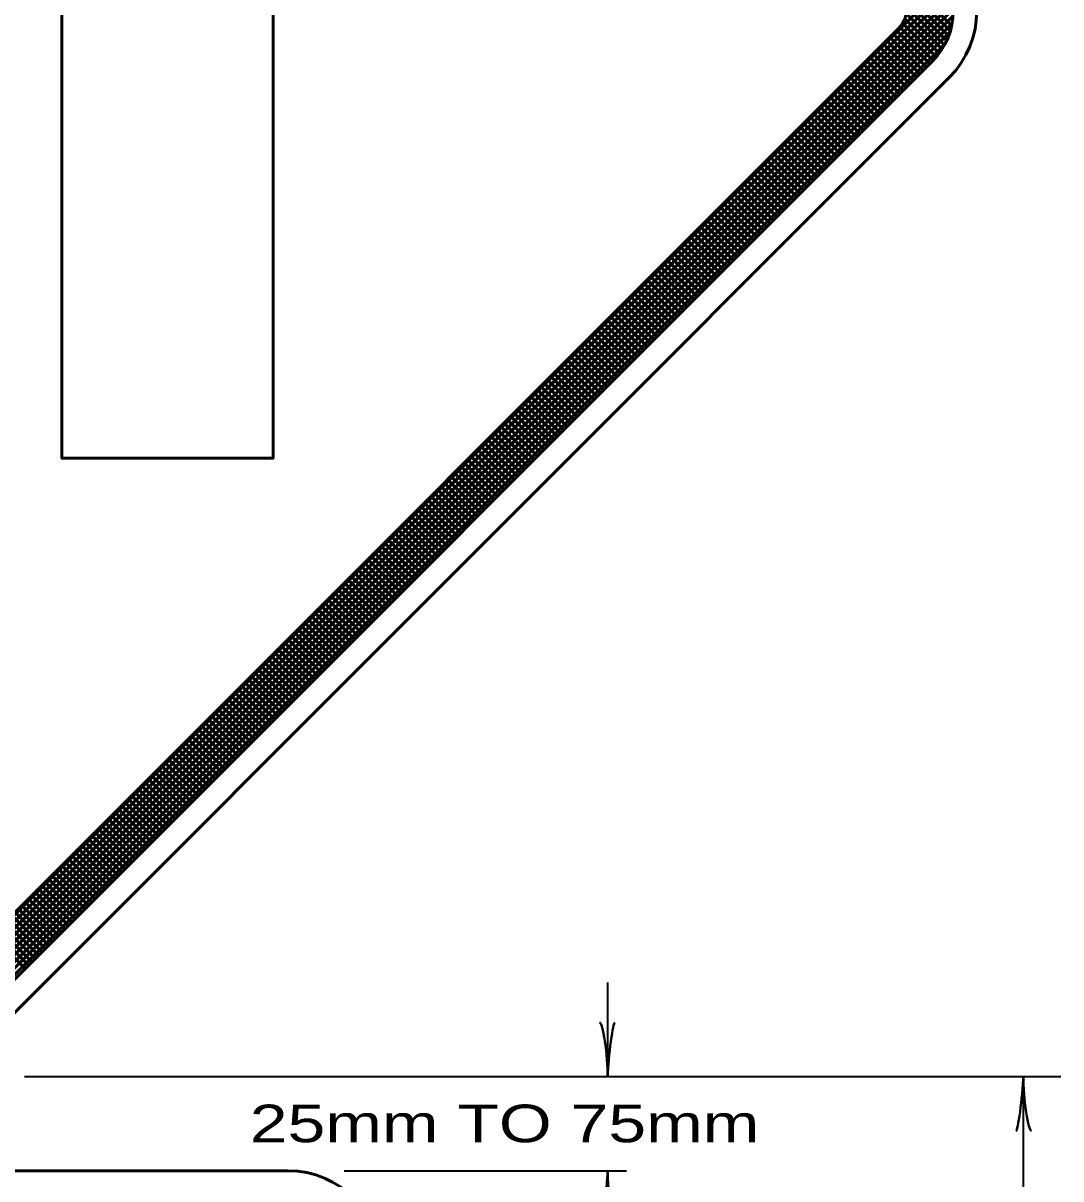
# Model space of a CAD drawing. Extents: x -87 to 768, y -466 to 78.
# Drawn here: x 67 to 133.2, y -203.4 to -129.7 of the extents above; entities that cross this region are included whole.
import ezdxf
from ezdxf.enums import TextEntityAlignment as Align

# ---------------------------------------------------------------- set-up
doc = ezdxf.new("R2010")
doc.units = 0
doc.header["$LTSCALE"] = 0.96
doc.layers.add('1', color=7, linetype='Continuous', lineweight=53)

msp = doc.modelspace()

# ---------------------------------------------------------------- linework, layer by layer
at = {"layer": '1'}
for p, q in [((126.2539, -129.9077), (58.9794, -62.6331)), ((125.936, -130.8625), (58.0238, -62.9503)), ((126.0612, -130.5635), (58.3227, -62.825)), ((126.1679, -130.2459), (58.6405, -62.7185)), ((58.0537, -195.0162), (125.9494, -127.1205)), ((58.3546, -195.1396), (126.0728, -127.4214)), ((58.6742, -195.2442), (126.1771, -127.7413)), ((59.0149, -195.3278), (126.2602, -128.0825)), ((59.3817, -195.3853), (126.3189, -128.448)), ((59.778, -195.4132), (126.3491, -128.8421)), ((125.7938, -131.1446), (123.3196, -128.6704)), ((60.2103, -195.4052), (126.3412, -129.2743)), ((125.4627, -131.662), (123.267, -129.4663)), ((125.6357, -131.4108), (123.3429, -129.118)), ((60.6917, -195.348), (126.2813, -129.7585)), ((60.9707, -191.9785), (122.9133, -130.0359)), ((61.2519, -195.2121), (126.1442, -130.3199)), ((124.6478, -132.5442), (122.5264, -130.4228)), ((124.86, -132.332), (122.7386, -130.2106)), ((125.0708, -132.1186), (122.9484, -129.9963)), ((125.2739, -131.8974), (123.1322, -129.7558)), ((61.9746, -194.9137), (125.8493, -131.039)), ((124.0114, -133.1806), (121.89, -131.0592)), ((124.2236, -132.9684), (122.1022, -130.847)), ((124.4357, -132.7563), (122.3143, -130.6349)), ((123.1629, -134.0291), (121.0415, -131.9077)), ((123.375, -133.817), (121.2536, -131.6956)), ((123.5872, -133.6048), (121.4658, -131.4834)), ((123.7993, -133.3927), (121.6779, -131.2713)), ((63.0921, -194.0999), (125.0347, -132.1573)), ((122.5265, -134.6655), (120.4051, -132.5441)), ((122.7386, -134.4534), (120.6172, -132.332)), ((122.9508, -134.2412), (120.8294, -132.1198)), ((126.0954, -133.218), (64.1528, -195.1606)), ((121.678, -135.514), (119.5566, -133.3926)), ((121.8901, -135.3019), (119.7687, -133.1805)), ((122.1022, -135.0898), (119.9808, -132.9684)), ((122.3144, -134.8776), (120.193, -132.7562)), ((121.0416, -136.1504), (118.9202, -134.029)), ((121.2537, -135.9383), (119.1323, -133.8169)), ((121.4658, -135.7262), (119.3444, -133.6048)), ((120.4052, -136.7868), (118.2838, -134.6654)), ((120.6173, -136.5747), (118.4959, -134.4533)), ((120.8294, -136.3626), (118.708, -134.2412)), ((119.5567, -137.6353), (117.4353, -135.5139)), ((119.7688, -137.4232), (117.6474, -135.3018)), ((119.9809, -137.2111), (117.8595, -135.0897)), ((120.193, -136.999), (118.0716, -134.8776)), ((118.9203, -138.2717), (116.7989, -136.1503)), ((119.1324, -138.0596), (117.011, -135.9382)), ((119.3445, -137.8475), (117.2231, -135.7261)), ((118.0717, -139.1203), (115.9503, -136.9989)), ((118.2839, -138.9081), (116.1625, -136.7867)), ((118.496, -138.696), (116.3746, -136.5746)), ((118.7081, -138.4839), (116.5867, -136.3625)), ((117.4353, -139.7567), (115.3139, -137.6353)), ((117.6475, -139.5445), (115.5261, -137.4231)), ((117.8596, -139.3324), (115.7382, -137.211)), ((116.5868, -140.6052), (114.4654, -138.4838)), ((116.7989, -140.3931), (114.6775, -138.2717)), ((117.0111, -140.1809), (114.8897, -138.0595)), ((117.2232, -139.9688), (115.1018, -137.8474)), ((115.9504, -141.2416), (113.829, -139.1202)), ((116.1625, -141.0295), (114.0411, -138.9081)), ((116.3747, -140.8173), (114.2533, -138.6959)), ((115.1019, -142.0901), (112.9805, -139.9687)), ((115.314, -141.878), (113.1926, -139.7566)), ((115.5261, -141.6659), (113.4047, -139.5445)), ((115.7383, -141.4537), (113.6169, -139.3323)), ((114.4655, -142.7265), (112.3441, -140.6051)), ((114.6776, -142.5144), (112.5562, -140.393)), ((114.8897, -142.3023), (112.7683, -140.1809)), ((113.617, -143.575), (111.4956, -141.4536)), ((113.8291, -143.3629), (111.7077, -141.2415)), ((114.0412, -143.1508), (111.9198, -141.0294)), ((114.2534, -142.9386), (112.132, -140.8172)), ((112.9806, -144.2114), (110.8592, -142.09)), ((113.1927, -143.9993), (111.0713, -141.8779)), ((113.4048, -143.7872), (111.2834, -141.6658)), ((112.132, -145.06), (110.0106, -142.9386)), ((112.3442, -144.8478), (110.2228, -142.7264)), ((112.5563, -144.6357), (110.4349, -142.5143)), ((112.7684, -144.4236), (110.647, -142.3022)), ((111.4956, -145.6964), (109.3742, -143.575)), ((111.7078, -145.4842), (109.5864, -143.3628)), ((111.9199, -145.2721), (109.7985, -143.1507)), ((110.6471, -146.5449), (108.5257, -144.4235)), ((110.8592, -146.3328), (108.7378, -144.2114)), ((111.0714, -146.1206), (108.95, -143.9992)), ((111.2835, -145.9085), (109.1621, -143.7871)), ((110.0107, -147.1813), (107.8893, -145.0599)), ((110.2228, -146.9692), (108.1014, -144.8478)), ((110.435, -146.757), (108.3136, -144.6356)), ((109.1622, -148.0298), (107.0408, -145.9084)), ((109.3743, -147.8177), (107.2529, -145.6963)), ((109.5864, -147.6056), (107.465, -145.4842)), ((109.7986, -147.3934), (107.6772, -145.272)), ((108.5258, -148.6662), (106.4044, -146.5448)), ((108.7379, -148.4541), (106.6165, -146.3327)), ((108.9501, -148.2419), (106.8287, -146.1205)), ((107.6773, -149.5147), (105.5559, -147.3933)), ((107.8894, -149.3026), (105.768, -147.1812)), ((108.1015, -149.0905), (105.9801, -146.9691)), ((108.3137, -148.8783), (106.1923, -146.7569)), ((107.0409, -150.1511), (104.9195, -148.0297)), ((107.253, -149.939), (105.1316, -147.8176)), ((107.4651, -149.7269), (105.3437, -147.6055)), ((106.4045, -150.7875), (104.2831, -148.6661)), ((106.6166, -150.5754), (104.4952, -148.454)), ((106.8287, -150.3633), (104.7073, -148.2419)), ((105.5559, -151.6361), (103.4345, -149.5147)), ((105.7681, -151.4239), (103.6467, -149.3025)), ((105.9802, -151.2118), (103.8588, -149.0904)), ((106.1923, -150.9997), (104.0709, -148.8783)), ((104.9195, -152.2725), (102.7981, -150.1511)), ((105.1317, -152.0603), (103.0103, -149.9389)), ((105.3438, -151.8482), (103.2224, -149.7268)), ((104.071, -153.121), (101.9496, -150.9996)), ((104.2831, -152.9089), (102.1617, -150.7875)), ((104.4953, -152.6967), (102.3739, -150.5753)), ((104.7074, -152.4846), (102.586, -150.3632)), ((103.4346, -153.7574), (101.3132, -151.636)), ((103.6468, -153.5452), (101.5254, -151.4238)), ((103.8589, -153.3331), (101.7375, -151.2117)), ((102.5861, -154.6059), (100.4647, -152.4845)), ((102.7982, -154.3938), (100.6768, -152.2724)), ((103.0104, -154.1816), (100.889, -152.0602)), ((103.2225, -153.9695), (101.1011, -151.8481)), ((101.9497, -155.2423), (99.8283, -153.1209)), ((102.1618, -155.0302), (100.0404, -152.9088)), ((102.374, -154.818), (100.2526, -152.6966)), ((101.1012, -156.0908), (98.9798, -153.9694)), ((101.3133, -155.8787), (99.1919, -153.7573)), ((101.5254, -155.6666), (99.404, -153.5452)), ((101.7376, -155.4544), (99.6162, -153.333)), ((100.4648, -156.7272), (98.3434, -154.6058)), ((100.6769, -156.5151), (98.5555, -154.3937)), ((100.889, -156.303), (98.7676, -154.1816)), ((99.6162, -157.5758), (97.4948, -155.4544)), ((99.8284, -157.3636), (97.707, -155.2422)), ((100.0405, -157.1515), (97.9191, -155.0301)), ((100.2526, -156.9394), (98.1312, -154.818)), ((98.9798, -158.2122), (96.8584, -156.0908)), ((99.192, -158), (97.0706, -155.8786)), ((99.4041, -157.7879), (97.2827, -155.6665)), ((98.1313, -159.0607), (96.0099, -156.9393)), ((98.3434, -158.8486), (96.222, -156.7272)), ((98.5556, -158.6364), (96.4342, -156.515)), ((98.7677, -158.4243), (96.6463, -156.3029)), ((97.4949, -159.6971), (95.3735, -157.5757)), ((97.7071, -159.4849), (95.5857, -157.3635)), ((97.9192, -159.2728), (95.7978, -157.1514)), ((96.6464, -160.5456), (94.525, -158.4242)), ((96.8585, -160.3335), (94.7371, -158.2121)), ((97.0707, -160.1213), (94.9493, -157.9999)), ((97.2828, -159.9092), (95.1614, -157.7878)), ((96.01, -161.182), (93.8886, -159.0606)), ((96.2221, -160.9699), (94.1007, -158.8485)), ((96.4343, -160.7577), (94.3129, -158.6363)), ((95.1615, -162.0305), (93.0401, -159.9091)), ((95.3736, -161.8184), (93.2522, -159.697)), ((95.5857, -161.6063), (93.4643, -159.4849)), ((95.7979, -161.3941), (93.6765, -159.2727)), ((94.5251, -162.6669), (92.4037, -160.5455)), ((94.7372, -162.4548), (92.6158, -160.3334)), ((94.9493, -162.2427), (92.8279, -160.1213)), ((93.6765, -163.5155), (91.5551, -161.3941)), ((93.8887, -163.3033), (91.7673, -161.1819)), ((94.1008, -163.0912), (91.9794, -160.9698)), ((94.3129, -162.8791), (92.1915, -160.7577)), ((93.0401, -164.1519), (90.9187, -162.0305)), ((93.2523, -163.9397), (91.1309, -161.8183)), ((93.4644, -163.7276), (91.343, -161.6062)), ((92.4038, -164.7882), (90.2824, -162.6668)), ((92.6159, -164.5761), (90.4945, -162.4547)), ((92.828, -164.364), (90.7066, -162.2426)), ((91.5552, -165.6368), (89.4338, -163.5154)), ((91.7674, -165.4246), (89.646, -163.3032)), ((91.9795, -165.2125), (89.8581, -163.0911)), ((92.1916, -165.0004), (90.0702, -162.879)), ((90.9188, -166.2732), (88.7974, -164.1518)), ((91.131, -166.061), (89.0096, -163.9396)), ((91.3431, -165.8489), (89.2217, -163.7275)), ((90.0703, -167.1217), (87.9489, -165.0003)), ((90.2824, -166.9096), (88.161, -164.7882)), ((90.4946, -166.6974), (88.3732, -164.576)), ((90.7067, -166.4853), (88.5853, -164.3639)), ((89.4339, -167.7581), (87.3125, -165.6367)), ((89.646, -167.546), (87.5246, -165.4246)), ((89.8582, -167.3338), (87.7368, -165.2124)), ((88.5854, -168.6066), (86.464, -166.4852)), ((88.7975, -168.3945), (86.6761, -166.2731)), ((89.0096, -168.1824), (86.8882, -166.061)), ((89.2218, -167.9702), (87.1004, -165.8488)), ((87.949, -169.243), (85.8276, -167.1216)), ((88.1611, -169.0309), (86.0397, -166.9095)), ((88.3732, -168.8188), (86.2518, -166.6974)), ((87.1005, -170.0915), (84.9791, -167.9701)), ((87.3126, -169.8794), (85.1912, -167.758)), ((87.5247, -169.6673), (85.4033, -167.5459)), ((87.7368, -169.4552), (85.6154, -167.3338)), ((86.4641, -170.7279), (84.3427, -168.6065)), ((86.6762, -170.5158), (84.5548, -168.3944)), ((86.8883, -170.3037), (84.7669, -168.1823)), ((85.6155, -171.5765), (83.4941, -169.4551)), ((85.8277, -171.3643), (83.7063, -169.2429)), ((86.0398, -171.1522), (83.9184, -169.0308)), ((86.2519, -170.9401), (84.1305, -168.8187)), ((84.9791, -172.2129), (82.8577, -170.0915)), ((85.1913, -172.0007), (83.0699, -169.8793)), ((85.4034, -171.7886), (83.282, -169.6672)), ((84.1306, -173.0614), (82.0092, -170.94)), ((84.3427, -172.8493), (82.2213, -170.7279)), ((84.5549, -172.6371), (82.4335, -170.5157)), ((84.767, -172.425), (82.6456, -170.3036)), ((83.4942, -173.6978), (81.3728, -171.5764)), ((83.7063, -173.4857), (81.5849, -171.3643)), ((83.9185, -173.2735), (81.7971, -171.1521)), ((82.6457, -174.5463), (80.5243, -172.4249)), ((82.8578, -174.3342), (80.7364, -172.2128)), ((83.0699, -174.1221), (80.9485, -172.0007)), ((83.2821, -173.9099), (81.1607, -171.7885)), ((82.0093, -175.1827), (79.8879, -173.0613)), ((82.2214, -174.9706), (80.1, -172.8492)), ((82.4335, -174.7585), (80.3121, -172.6371)), ((81.1608, -176.0312), (79.0394, -173.9098)), ((81.3729, -175.8191), (79.2515, -173.6977)), ((81.585, -175.607), (79.4636, -173.4856)), ((81.7972, -175.3948), (79.6758, -173.2734)), ((80.5244, -176.6676), (78.403, -174.5462)), ((80.7365, -176.4555), (78.6151, -174.3341)), ((80.9486, -176.2434), (78.8272, -174.122)), ((79.6758, -177.5162), (77.5544, -175.3948)), ((79.888, -177.304), (77.7666, -175.1826)), ((80.1001, -177.0919), (77.9787, -174.9705)), ((80.3122, -176.8798), (78.1908, -174.7584)), ((79.0394, -178.1526), (76.918, -176.0312)), ((79.2516, -177.9404), (77.1302, -175.819)), ((79.4637, -177.7283), (77.3423, -175.6069)), ((78.403, -178.789), (76.2816, -176.6676)), ((78.6152, -178.5768), (76.4938, -176.4554)), ((78.8273, -178.3647), (76.7059, -176.2433)), ((77.5545, -179.6375), (75.4331, -177.5161)), ((77.7666, -179.4254), (75.6452, -177.304)), ((77.9788, -179.2132), (75.8574, -177.0918)), ((78.1909, -179.0011), (76.0695, -176.8797)), ((76.9181, -180.2739), (74.7967, -178.1525)), ((77.1302, -180.0618), (75.0088, -177.9404)), ((77.3424, -179.8496), (75.221, -177.7282)), ((76.0696, -181.1224), (73.9482, -179.001)), ((76.2817, -180.9103), (74.1603, -178.7889)), ((76.4938, -180.6982), (74.3724, -178.5768)), ((76.706, -180.486), (74.5846, -178.3646)), ((75.4332, -181.7588), (73.3118, -179.6374)), ((75.6453, -181.5467), (73.5239, -179.4253)), ((75.8575, -181.3345), (73.7361, -179.2131)), ((74.5847, -182.6073), (72.4633, -180.4859)), ((74.7968, -182.3952), (72.6754, -180.2738)), ((75.0089, -182.1831), (72.8875, -180.0617)), ((75.2211, -181.9709), (73.0997, -179.8495)), ((73.9483, -183.2437), (71.8269, -181.1223)), ((74.1604, -183.0316), (72.039, -180.9102)), ((74.3725, -182.8195), (72.2511, -180.6981)), ((73.0997, -184.0923), (70.9783, -181.9709)), ((73.3119, -183.8801), (71.1905, -181.7587)), ((73.524, -183.668), (71.4026, -181.5466)), ((73.7361, -183.4559), (71.6147, -181.3345)), ((72.4633, -184.7287), (70.3419, -182.6073)), ((72.6755, -184.5165), (70.5541, -182.3951)), ((72.8876, -184.3044), (70.7662, -182.183)), ((71.6148, -185.5772), (69.4934, -183.4558)), ((71.8269, -185.3651), (69.7055, -183.2437)), ((72.0391, -185.1529), (69.9177, -183.0315)), ((72.2512, -184.9408), (70.1298, -182.8194)), ((70.9784, -186.2136), (68.857, -184.0922)), ((71.1905, -186.0015), (69.0691, -183.8801)), ((71.4027, -185.7893), (69.2813, -183.6679)), ((70.1299, -187.0621), (68.0085, -184.9407)), ((70.342, -186.85), (68.2206, -184.7286)), ((70.5542, -186.6378), (68.4328, -184.5164)), ((70.7663, -186.4257), (68.6449, -184.3043)), ((69.4935, -187.6985), (67.3721, -185.5771)), ((69.7056, -187.4864), (67.5842, -185.365)), ((69.9178, -187.2742), (67.7964, -185.1528)), ((68.645, -188.547), (66.5236, -186.4256)), ((68.8571, -188.3349), (66.7357, -186.2135)), ((69.0692, -188.1228), (66.9478, -186.0014)), ((69.2814, -187.9106), (67.16, -185.7892)), ((68.0086, -189.1834), (65.8872, -187.062)), ((68.2207, -188.9713), (66.0993, -186.8499)), ((68.4328, -188.7592), (66.3114, -186.6378)), ((67.16, -190.032), (65.0386, -187.9106)), ((67.3722, -189.8198), (65.2508, -187.6984)), ((67.5843, -189.6077), (65.4629, -187.4863)), ((67.7964, -189.3956), (65.675, -187.2742)), ((63.2102, -202.9179), (83.9102, -202.9179))]:
    msp.add_line(p, q, dxfattribs=at)
at = {"layer": '1', "lineweight": 35}
for p, q in [((104.3102, -190.9179), (104.3102, -196.9179)), ((67.1102, -196.9179), (133.2183, -196.9179)), ((130.8183, -196.9179), (130.8183, -207.6154)), ((87.5102, -202.9179), (105.5102, -202.9179)), ((104.3102, -202.9179), (104.3102, -208.9179))]:
    msp.add_line(p, q, dxfattribs=at)
at = {"layer": '1'}
msp.add_lwpolyline([(82.9775, -122.1806), (82.9775, -157.489), (69.5029, -157.489), (69.5029, -155.1658), (69.5029, -127.2552)], dxfattribs=at)
for centre, radius, start, end in [((121.8527, -128.9754), 6, 315, 45), ((121.8527, -128.9754), 4.5, 315, 45), ((121.8527, -128.9754), 1.5, 315, 45), ((83.9102, -208.9179), 6, 0, 90)]:
    msp.add_arc(centre, radius, start, end, dxfattribs=at)
at = {"layer": '1', "lineweight": 40}
for centre, major_axis, ratio, start_param, end_param in [((103.9786, -195.6085), (0.1874, -2.1428), 0.122415, 0.8963533, 3.1415927), ((103.9786, -195.6085), (0.1874, -2.1428), 0.122415, 0.8963533, 3.1415927), ((104.5641, -195.5733), (-0.2108, -2.1077), 0.07063, 3.1407148, 5.41811), ((104.5641, -195.5733), (-0.2108, -2.1077), 0.07063, 3.1407148, 5.41811), ((130.5644, -198.2625), (0.2108, 2.1077), 0.07063, 3.1407148, 5.41811), ((130.5644, -198.2625), (0.2108, 2.1077), 0.07063, 3.1407148, 5.41811), ((131.1499, -198.2273), (-0.1874, 2.1428), 0.122415, 0.8963533, 3.1415927), ((131.1499, -198.2273), (-0.1874, 2.1428), 0.122415, 0.8963533, 3.1415927), ((104.0563, -204.2625), (0.2108, 2.1077), 0.07063, 3.1407148, 5.41811), ((104.6418, -204.2273), (-0.1874, 2.1428), 0.122415, 0.8963533, 3.1415927)]:
    msp.add_ellipse(centre, major_axis=major_axis, ratio=ratio, start_param=start_param, end_param=end_param, dxfattribs=at)

# ---------------------------------------------------------------- texts
at = {"layer": '1', "width": 1.35}
msp.add_text('25mm TO 75mm', height=2.4, dxfattribs=at).set_placement((97.7351, -201.1057), align=Align.CENTER)

doc.saveas('drawing.dxf')
